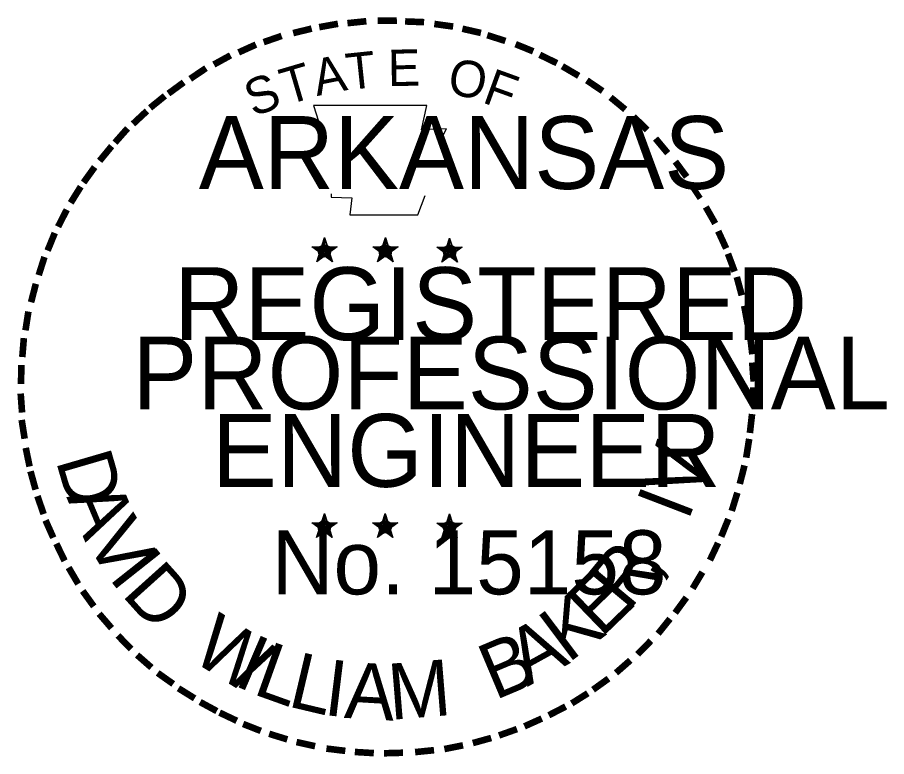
# Model space of a CAD drawing. Extents: x 34757 to 38214, y 51436 to 59430.
# Drawn here: x 36491.2 to 36612.9, y 52583.6 to 52687.1 of the extents above; entities that cross this region are included whole.
import ezdxf

# ---------------------------------------------------------------- set-up
doc = ezdxf.new("R2010")
doc.units = 0
doc.layers.add('R_Border PE', color=7, linetype='Continuous')
doc.layers.add('SHET_Stamp-PE-Chief-Eng', color=7, linetype='Continuous')

msp = doc.modelspace()

# ---------------------------------------------------------------- linework, layer by layer
at = {"layer": 'R_Border PE'}
for p, q in [((36534.19, 52656.26), (36533.98, 52654.97)), ((36534.19, 52654.4), (36534.19, 52656.26)), ((36534.19, 52656.26), (36534.44, 52654.98)), ((36542.71, 52656.26), (36542.5, 52654.97)), ((36542.71, 52654.4), (36542.71, 52656.26)), ((36542.71, 52656.26), (36542.96, 52654.98)), ((36551.7, 52656.2), (36551.49, 52654.91)), ((36551.7, 52654.34), (36551.7, 52656.2)), ((36551.7, 52656.2), (36551.95, 52654.92)), ((36532.41, 52654.96), (36534.19, 52654.4)), ((36532.41, 52654.96), (36533.7, 52654.73)), ((36532.41, 52654.96), (36533.62, 52654.34)), ((36535.96, 52654.96), (36534.19, 52654.4)), ((36535.96, 52654.96), (36534.5, 52654.71)), ((36535.96, 52654.96), (36534.92, 52654.44)), ((36540.93, 52654.96), (36542.71, 52654.4)), ((36540.93, 52654.96), (36542.22, 52654.73)), ((36540.93, 52654.96), (36542.13, 52654.34)), ((36544.48, 52654.96), (36542.71, 52654.4)), ((36544.48, 52654.96), (36543.02, 52654.71)), ((36544.48, 52654.96), (36543.44, 52654.44)), ((36549.92, 52654.9), (36551.7, 52654.34)), ((36549.92, 52654.9), (36551.21, 52654.67)), ((36549.92, 52654.9), (36551.13, 52654.28)), ((36553.47, 52654.9), (36551.7, 52654.34)), ((36553.47, 52654.9), (36552.01, 52654.65)), ((36553.47, 52654.9), (36552.43, 52654.38)), ((36533.09, 52652.88), (36534.19, 52654.4)), ((36533.09, 52652.88), (36533.73, 52654.13)), ((36533.09, 52652.88), (36534.18, 52653.99)), ((36535.28, 52652.88), (36534.18, 52653.97)), ((36535.28, 52652.88), (36534.19, 52654.4)), ((36535.28, 52652.88), (36534.58, 52654.37)), ((36541.6, 52652.88), (36542.71, 52654.4)), ((36541.6, 52652.88), (36542.25, 52654.13)), ((36541.6, 52652.88), (36542.7, 52653.99)), ((36543.79, 52652.88), (36542.7, 52653.97)), ((36543.79, 52652.88), (36542.71, 52654.4)), ((36543.79, 52652.88), (36543.09, 52654.37)), ((36550.6, 52652.82), (36551.7, 52654.34)), ((36550.6, 52652.82), (36551.24, 52654.06)), ((36550.6, 52652.82), (36551.69, 52653.93)), ((36552.79, 52652.82), (36551.69, 52653.91)), ((36552.79, 52652.82), (36551.7, 52654.34)), ((36552.79, 52652.82), (36552.09, 52654.3)), ((36534.17, 52617.64), (36533.96, 52616.35)), ((36534.17, 52615.77), (36534.17, 52617.64)), ((36534.17, 52617.64), (36534.42, 52616.36)), ((36542.68, 52617.64), (36542.47, 52616.35)), ((36542.68, 52615.77), (36542.68, 52617.64)), ((36542.68, 52617.64), (36542.93, 52616.36)), ((36551.69, 52617.59), (36551.48, 52616.3)), ((36551.69, 52615.72), (36551.69, 52617.59)), ((36551.69, 52617.59), (36551.94, 52616.31)), ((36532.39, 52616.34), (36534.17, 52615.77)), ((36532.39, 52616.34), (36533.68, 52616.11)), ((36532.39, 52616.34), (36533.6, 52615.72)), ((36533.07, 52614.26), (36534.17, 52615.77)), ((36535.94, 52616.34), (36534.17, 52615.77)), ((36535.26, 52614.26), (36534.17, 52615.77)), ((36535.94, 52616.34), (36534.48, 52616.09)), ((36535.26, 52614.26), (36534.56, 52615.74)), ((36535.94, 52616.34), (36534.9, 52615.82)), ((36540.9, 52616.34), (36542.68, 52615.77)), ((36540.9, 52616.34), (36542.19, 52616.11)), ((36540.9, 52616.34), (36542.11, 52615.72)), ((36541.58, 52614.26), (36542.68, 52615.77)), ((36544.45, 52616.34), (36542.68, 52615.77)), ((36543.77, 52614.26), (36542.68, 52615.77)), ((36544.45, 52616.34), (36542.99, 52616.09)), ((36543.77, 52614.26), (36543.07, 52615.74)), ((36544.45, 52616.34), (36543.41, 52615.82)), ((36549.91, 52616.29), (36551.69, 52615.72)), ((36549.91, 52616.29), (36551.2, 52616.06)), ((36549.91, 52616.29), (36551.12, 52615.67)), ((36553.46, 52616.29), (36551.69, 52615.72)), ((36553.46, 52616.29), (36552, 52616.04)), ((36553.46, 52616.29), (36552.42, 52615.77)), ((36533.07, 52614.26), (36533.71, 52615.5)), ((36533.07, 52614.26), (36534.16, 52615.37)), ((36535.26, 52614.26), (36534.16, 52615.35)), ((36541.58, 52614.26), (36542.22, 52615.5)), ((36541.58, 52614.26), (36542.67, 52615.37)), ((36543.77, 52614.26), (36542.67, 52615.35)), ((36550.59, 52614.21), (36551.69, 52615.72)), ((36550.59, 52614.21), (36551.23, 52615.45)), ((36550.59, 52614.21), (36551.68, 52615.32)), ((36552.78, 52614.21), (36551.68, 52615.3)), ((36552.78, 52614.21), (36551.69, 52615.72)), ((36552.78, 52614.21), (36552.08, 52615.69))]:
    msp.add_line(p, q, dxfattribs=at)
for points in [[(36532.62, 52674.74), (36533.99, 52670.52)], [(36550.52, 52670.04), (36551.25, 52671.49), (36547.76, 52671.36), (36548.51, 52674.74), (36532.62, 52674.74)], [(36535.13, 52662.38), (36535.13, 52661.94), (36538, 52661.84), (36537.72, 52659.43), (36547.26, 52659.43), (36548.29, 52662.16)], [(36542.71, 52656.26), (36543.79, 52652.88), (36540.93, 52654.96), (36544.48, 52654.96), (36541.6, 52652.88), (36542.71, 52656.26)], [(36551.7, 52656.2), (36552.79, 52652.82), (36549.92, 52654.9), (36553.47, 52654.9), (36550.6, 52652.82), (36551.7, 52656.2)], [(36534.17, 52617.64), (36535.26, 52614.26), (36532.39, 52616.34), (36535.94, 52616.34), (36533.07, 52614.26), (36534.17, 52617.64)], [(36542.68, 52617.64), (36543.77, 52614.26), (36540.9, 52616.34), (36544.45, 52616.34), (36541.58, 52614.26), (36542.68, 52617.64)], [(36551.69, 52617.59), (36552.78, 52614.21), (36549.91, 52616.29), (36553.46, 52616.29), (36550.59, 52614.21), (36551.69, 52617.59)]]:
    msp.add_lwpolyline(points, dxfattribs=at)
for centre, radius in [((36534.18, 52654.39), 0.878), ((36534.18, 52654.39), 0.737), ((36534.18, 52654.39), 0.59), ((36534.18, 52654.39), 0.505), ((36534.18, 52654.39), 0.381), ((36542.7, 52654.39), 0.878), ((36542.7, 52654.39), 0.737), ((36542.7, 52654.39), 0.59), ((36542.7, 52654.39), 0.505), ((36542.7, 52654.39), 0.381), ((36551.7, 52654.33), 0.878), ((36551.7, 52654.33), 0.737), ((36551.7, 52654.33), 0.59), ((36551.7, 52654.33), 0.505), ((36551.7, 52654.33), 0.381), ((36534.18, 52654.39), 0.253), ((36534.18, 52654.39), 0.151), ((36542.7, 52654.39), 0.253), ((36542.7, 52654.39), 0.151), ((36551.7, 52654.33), 0.253), ((36551.7, 52654.33), 0.151), ((36534.16, 52615.77), 0.878), ((36534.16, 52615.77), 0.737), ((36534.16, 52615.77), 0.59), ((36534.16, 52615.77), 0.505), ((36534.16, 52615.77), 0.381), ((36534.16, 52615.77), 0.253), ((36534.16, 52615.77), 0.151), ((36542.68, 52615.77), 0.878), ((36542.68, 52615.77), 0.737), ((36542.68, 52615.77), 0.59), ((36542.68, 52615.77), 0.505), ((36542.68, 52615.77), 0.381), ((36542.68, 52615.77), 0.253), ((36542.68, 52615.77), 0.151), ((36551.69, 52615.72), 0.878), ((36551.69, 52615.72), 0.737), ((36551.69, 52615.72), 0.59), ((36551.69, 52615.72), 0.505), ((36551.69, 52615.72), 0.381), ((36551.69, 52615.72), 0.253), ((36551.69, 52615.72), 0.151)]:
    msp.add_circle(centre, radius, dxfattribs=at)
at = {"layer": 'SHET_Stamp-PE-Chief-Eng'}
msp.add_lwpolyline([(36534.19, 52656.26), (36535.28, 52652.88), (36532.41, 52654.96), (36535.96, 52654.96), (36533.09, 52652.88), (36534.19, 52656.26)], dxfattribs=at)

# ---------------------------------------------------------------- texts
at = {"layer": 'R_Border PE'}
for s, height, rotation, p in [('-', 8.16, 10.2193, (36533.52, 52682.54)), ('-', 8.16, 5.8968, (36537.23, 52683.1)), ('-', 8.16, 0.1862, (36541.17, 52683.47)), ('-', 8.16, 357.743, (36544.86, 52683.4)), ('-', 8.16, 352.1617, (36548.65, 52683.12)), ('-', 8.16, 13.6302, (36530.06, 52681.72)), ('-', 8.16, 347.2049, (36552.32, 52682.54)), ('-', 8.16, 19.1761, (36526.23, 52680.49)), ('-', 8.16, 342.3362, (36555.56, 52681.75)), ('-', 8.16, 24.3072, (36523, 52679.12)), ('-', 8.16, 337.8551, (36559.31, 52680.61)), ('-', 8.16, 28.7918, (36519.77, 52677.5)), ('A', 5.1, 11.2132, (36533.1, 52676.07)), ('T', 5.1, 6.0228, (36537.43, 52676.91)), ('E', 5.1, 0.8323, (36543.07, 52677.47)), ('-', 8.16, 334.1211, (36562.52, 52679.23)), ('-', 8.16, 34.0636, (36516.73, 52675.61)), ('T', 5.1, 16.4036, (36528.89, 52674.79)), ('O', 5.1, 350.4515, (36551.25, 52676.4)), ('-', 8.16, 329.6409, (36565.48, 52677.78)), ('S', 5.1, 21.594, (36524.23, 52673.1)), ('F', 5.1, 340.0707, (36556.11, 52675.24)), ('-', 8.16, 36.2317, (36513.78, 52673.6)), ('-', 8.16, 325.8627, (36568.76, 52675.94)), ('-', 8.16, 38.9507, (36511.35, 52671.67)), ('-', 8.16, 320.5297, (36571.87, 52673.77)), ('-', 8.16, 42.9622, (36509.14, 52669.54)), ('-', 8.16, 315.5786, (36574.92, 52671.28)), ('-', 8.16, 48.4231, (36506.86, 52667.11)), ('-', 8.16, 50.6142, (36504.8, 52664.63)), ('-', 8.16, 309.8797, (36577.82, 52668.48)), ('-', 8.16, 306.6522, (36580.5, 52665.41)), ('-', 8.16, 54.2325, (36502.7, 52661.74)), ('-', 8.16, 58.0706, (36501.04, 52659.05)), ('-', 7.14, 303.6753, (36582.98, 52662.51)), ('-', 8.16, 299.6684, (36584.61, 52659.41)), ('-', 8.16, 62.8713, (36499.44, 52655.92)), ('-', 8.16, 294.6628, (36586.26, 52656.29)), ('-', 8.16, 67.7743, (36498.12, 52652.8)), ('-', 8.16, 72.3945, (36497, 52649.59)), ('-', 8.16, 290.5728, (36587.57, 52653.35)), ('-', 8.16, 75.461, (36496, 52645.95)), ('-', 8.16, 285.1233, (36588.76, 52650.39)), ('-', 8.16, 280.5493, (36589.78, 52646.61)), ('-', 8.16, 81.2013, (36495.33, 52642.31)), ('-', 8.16, 276.5962, (36590.61, 52642.69)), ('-', 8.16, 85.1863, (36494.94, 52638.79)), ('-', 8.16, 89.0622, (36494.81, 52635.21)), ('-', 8.16, 274.3301, (36590.91, 52639.01)), ('-', 8.16, 269.9407, (36591.09, 52635.79)), ('-', 8.16, 94.1959, (36494.99, 52631.51)), ('-', 8.16, 263.5172, (36590.99, 52632.39)), ('-', 8.16, 98.9479, (36495.36, 52628.11)), ('V', 7.85, 72.6573, (36586.22, 52619.16)), ('-', 8.16, 260.9953, (36590.63, 52629.05)), ('-', 8.16, 101.7149, (36496.05, 52624.37)), ('D', 7.85, 286.2848, (36496.5, 52625.08)), ('-', 8.16, 255.7626, (36590.07, 52625.6)), ('-', 8.16, 105.4578, (36496.87, 52621.34)), ('I', 7.85, 69.0301, (36585.08, 52616.41)), ('-', 8.16, 252.8681, (36589.14, 52621.93)), ('-', 8.16, 109.0874, (36497.97, 52618.12)), ('A', 7.85, 292.7835, (36497.99, 52619.97)), ('V', 7.85, 300.7936, (36500.61, 52613.95)), ('-', 8.16, 247.8887, (36588.01, 52618.49)), ('-', 8.16, 114.0643, (36499.26, 52615.08)), ('-', 8.16, 115.7289, (36500.82, 52611.93)), ('-', 8.16, 244.6197, (36586.67, 52615.29)), ('I', 7.85, 308.3502, (36503.83, 52608.67)), ('R', 7.85, 50.3651, (36576.67, 52603.72)), ('D', 7.85, 311.9774, (36505.62, 52606.29)), ('-', 8.16, 120.4471, (36502.64, 52608.94)), ('E', 7.85, 44.0175, (36572.92, 52600.11)), (',', 7.85, 57.4684, (36580.35, 52608.22)), ('-', 8.16, 239.0712, (36584.66, 52611.45)), ('-', 8.16, 125.8934, (36504.7, 52606.08)), ('K', 7.85, 36.9143, (36568.29, 52596.59)), ('-', 8.16, 233.8452, (36582.61, 52608.12)), ('-', 8.16, 130.7181, (36507.05, 52603.26)), ('W', 7.85, 328.0731, (36515.2, 52597.28)), ('-', 8.16, 231.2538, (36580.42, 52605.23)), ('A', 7.85, 28.9042, (36562.59, 52593.34)), ('-', 8.16, 134.2238, (36509.69, 52600.49)), ('I', 7.85, 336.6877, (36521.25, 52593.67)), ('B', 7.85, 22.8589, (36558.02, 52591.43)), ('-', 8.16, 225.7653, (36577.98, 52602.36)), ('L', 7.85, 340.3149, (36523.95, 52592.42)), ('-', 8.16, 138.9338, (36512.37, 52598.12)), ('L', 7.85, 346.6625, (36528.85, 52590.66)), ('I', 7.85, 353.0101, (36533.91, 52589.46)), ('A', 7.85, 356.6373, (36536.85, 52589.02)), ('M', 7.85, 4.6473, (36543.4, 52588.72)), ('-', 8.16, 221.0851, (36575.31, 52599.76)), ('-', 8.16, 144.6463, (36515.2, 52596.05)), ('-', 8.16, 215.7363, (36572.51, 52597.35)), ('-', 8.16, 148.0898, (36518.06, 52594.16)), ('-', 8.16, 212.2491, (36569.79, 52595.38)), ('-', 8.16, 151.5704, (36521.02, 52592.5)), ('-', 8.16, 154.6002, (36523.68, 52591.24)), ('-', 8.16, 207.3568, (36566.94, 52593.62)), ('-', 8.16, 204.2516, (36563.76, 52591.99)), ('-', 8.16, 158.5612, (36526.86, 52589.94)), ('-', 8.16, 199.4643, (36560.54, 52590.57)), ('-', 8.16, 162.7983, (36530.36, 52588.86)), ('-', 8.16, 195.4743, (36557.15, 52589.36)), ('-', 8.16, 167.5555, (36534.01, 52588.02)), ('-', 8.16, 191.2858, (36553.44, 52588.35)), ('-', 8.16, 173.1155, (36537.95, 52587.46)), ('-', 8.16, 176.5183, (36541.76, 52587.19)), ('-', 8.16, 181.5918, (36545.56, 52587.29)), ('-', 8.16, 185.8167, (36549.68, 52587.67))]:
    msp.add_text(s, height=height, rotation=rotation, dxfattribs=at).set_placement(p)
for s, height, p in [('ARKANSAS', 10.2, (36516.57, 52663.07)), ('REGISTERED', 10.2, (36513.11, 52641.91)), ('PROFESSIONAL', 10.1998, (36507.26, 52632.2)), ('ENGINEER', 10.2, (36518.41, 52621.36)), ('No. 15158', 8.961, (36526.78, 52606.31)), ('AAMU', 0.000102, (36542.34, 52588.7))]:
    msp.add_text(s, height=height, dxfattribs=at).set_placement(p)

doc.saveas('drawing.dxf')
